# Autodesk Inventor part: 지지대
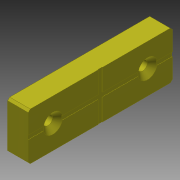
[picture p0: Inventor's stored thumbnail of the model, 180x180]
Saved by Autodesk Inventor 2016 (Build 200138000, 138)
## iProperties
Created: 2017-04
Part Number: 지지대
Material: 강철
Document SubType Name: Modeling
Designer: mduedu
Density: 7.85 g/cm^3
Mass: 97.8484 g
Surface Area: 48.4895 cm^2
Volume: 12.4648 cm^3
Appearance: 밝은 황색
Author: mduedu
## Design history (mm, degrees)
sketch "스케치1"
  geometry: L1 (23, -35)-(23, 35); L2 (0, -35)-(0, 35); L3 (0, 35)-(23, 35); L4 (0, -35)-(23, -35); 2 further points
  constraints: 8 end point, 2 parallel, 1 coincident, 1 midpoint, 1 perpendicular, 1 vertical
  dimensions: "d1" = 23 distance between parallel lines of L2 L1; "d15" = 70 distance of L1.start L1.end
extrude "돌출1" new body sketch "스케치1" distance "d2" = 8; taper "d3" = 0 deg
chamfer "모따기2" distance "d16" = 1; stored, may be unused: second distance "d17" = 2, angle "d18" = 45 deg
sketch "스케치2"
  geometry: L1 (1, -35)-(22, -35) reference; L2 (23, -34)-(23, 34) reference; L3 (22, 35)-(1, 35) reference; L4 (0, 34)-(0, -34) reference; L5 (11.5, 35)-(11.5, -35); L6 (23, 0)-(0, 0); L7 (1, -35)-(0, -34) reference; L8 (23, -34)-(22, -35) reference; L9 (22, 35)-(23, 34) reference; L10 (0, 34)-(1, 35) reference; 2 further points
  constraints: 4 end point, 4 midpoint, 1 point on line, 1 symmetric about line
  dimensions: "d7" = 12 distance from line of point (11.5, 23) L3
  node "투영된 루프1"
sketch "스케치3"
  geometry: 4 further points
  constraints: 2 coincident
hole "구멍1" sketch "스케치3" at (11.5, 23), (11.5, -23) diameter "d8" = 4.5; stored, may be unused: countersink angle "d12" = 90 deg, drill point angle "d14" = 0 deg; dims "d9" = 6, "d10" = 9.4, "d11" = 2, "d13" = 8
sketch "스케치4"
  geometry: L1 (-35, 22)-(-35, 1) reference; L2 (35, 1)-(35, 22) reference; L3 (34, 23)-(-34, 23) reference; L4 (-34, 0)-(34, 0) reference; L5 (-35, 11.5)-(35, 11.5); L6 (0, 23)-(0, 0); L7 (-35, 12.5)-(35, 12.5); L8 (-35, 10.5)-(35, 10.5); L9 (-1, 23)-(-1, 0); L10 (1, 23)-(1, 0)
  constraints: 12 end point, 8 point on line, 4 parallel, 3 midpoint, 3 perpendicular
  dimensions: "d19" = 1 distance between parallel lines of L7 L5; "d21" = 1 distance between parallel lines of L8 L5; "d22" = 1 distance between parallel lines of L9 L6; "d23" = 1 distance between parallel lines of L10 L6
extrude "돌출2" cut sketch "스케치4" distance "d24" = 0.2; taper "d25" = 0 deg
extrude "돌출3" cut sketch "스케치4" distance "d26" = 0.2; taper "d27" = 0 deg
fillet "모깎기1" dims "d28" = 0.2
node "솔리드2"
node "솔리드1"
